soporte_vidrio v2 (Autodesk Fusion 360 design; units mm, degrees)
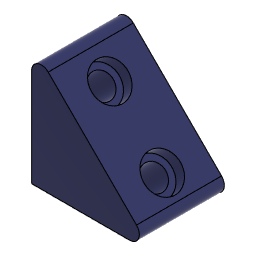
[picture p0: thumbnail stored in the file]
sketch "Sketch1" plane through (0, 0, 0) normal (0, 1, 0) x axis (1, 0, 0)
  line L1 (50, 0) -> (0, 0)
  line L2 (0, 0) -> (0, -50)
  line L3 (50, 0) -> (0, -50)
  point P1 (0, 0)
  point P2 (0, 0)
  horizontal L1
  vertical L2
  coincident P1 P2
extrude "Extrude1" new body sketch "Sketch1" along normal blind 35
fillet "Fillet1" radius 4
fillet "Fillet2" radius 4
sketch "Sketch2" plane through (25, 0, 25) normal (0.7071, 0, 0.7071) x axis (0, 1, 0)
  line L1 (35, -25.6985) -> (0, -25.6985)
  line L2 (35, 25.6985) -> (35, -25.6985)
  line L3 (0, 25.6985) -> (35, 25.6985)
  line L4 (0, -25.6985) -> (0, 25.6985)
  circle C1 centre (17.3639, 14.4089) radius 5
  circle C2 centre (17.2701, -16.2573) radius 5
  dimension "d7" diameter C1 = 10
  dimension "d8" diameter C2 = 10
extrude "Extrude2" cut sketch "Sketch2" profile of C1 C2 against normal blind 35
sketch "Sketch3" plane through (25, 0, 25) normal (0.7071, 0, 0.7071) x axis (0, 1, 0)
  line L1 (35, -25.6985) -> (0, -25.6985)
  line L2 (35, 25.6985) -> (35, -25.6985)
  line L3 (0, 25.6985) -> (35, 25.6985)
  line L4 (0, -25.6985) -> (0, 25.6985)
  circle C1 centre (17.3639, 14.4089) radius 5
  circle C2 centre (17.2701, -16.2573) radius 5
  circle C3 centre (17.3639, 14.4089) radius 7.5
  circle C4 centre (17.2701, -16.2573) radius 7.5
  concentric C1 C3
  concentric C2 C4
  dimension "d11" diameter C3 = 15
  dimension "d12" diameter C4 = 15
extrude "Extrude3" cut sketch "Sketch3" profile of C1 C2 C3 C4 along normal blind 5 and against normal blind 5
